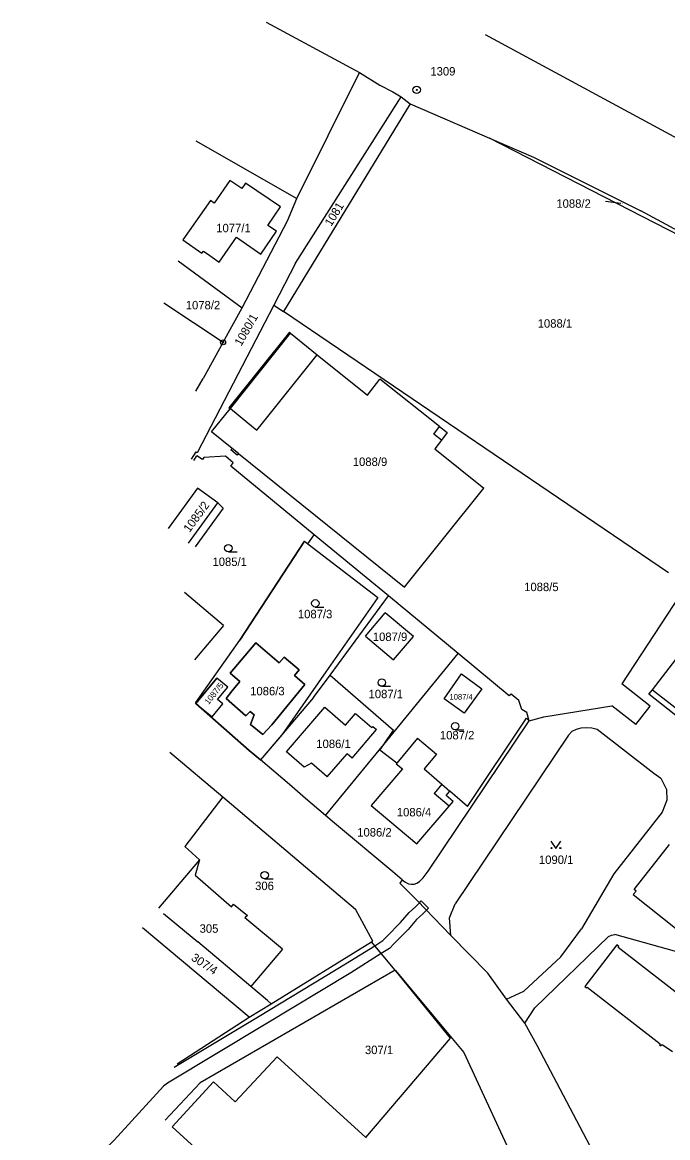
# Model space of a CAD drawing. Extents: x -621172 to -616925, y -1123899 to -1119548.
# Drawn here: x -619284.5 to -619154.3, y -1121538.1 to -1121313.2 of the extents above; entities that cross this region are included whole.
import ezdxf

# ---------------------------------------------------------------- set-up
doc = ezdxf.new("R2010")
doc.units = 0
for name, color, linetype in [('Vrstva 1', 7, 'Continuous'), ('Vrstva 16', 7, 'Continuous'), ('Vrstva 17', 7, 'Continuous'), ('Vrstva 18', 7, 'Continuous'), ('Vrstva 19', 7, 'Continuous'), ('Vrstva 24', 7, 'Continuous'), ('Vrstva 25', 7, 'Continuous'), ('Vrstva 4', 7, 'Continuous')]:
    doc.layers.add(name, color=color, linetype=linetype)

msp = doc.modelspace()

# ---------------------------------------------------------------- linework, layer by layer
at = {"layer": 'Vrstva 1'}
for points in [[(-619235.35, -1121313.15), (-619216.51, -1121323.27)], [(-619191.16, -1121315.58), (-619124.1, -1121351.82)], [(-619229.15, -1121348.66), (-619216.51, -1121323.27)], [(-619216.51, -1121323.27), (-619212.42, -1121325.82)], [(-619212.42, -1121325.82), (-619209.77, -1121327.14)], [(-619209.77, -1121327.14), (-619208.11, -1121328.19)], [(-619206.26, -1121329.56), (-619231.87, -1121371.5)], [(-619229.42, -1121361.74), (-619208.11, -1121328.19)], [(-619208.11, -1121328.19), (-619206.26, -1121329.56)], [(-619206.26, -1121329.56), (-619190.24, -1121336.5)], [(-619190.24, -1121336.5), (-619181.41, -1121340.33)], [(-619141.38, -1121361.62), (-619190.24, -1121336.5)], [(-619249.54, -1121337.02), (-619229.15, -1121348.66)], [(-619181.41, -1121340.33), (-619159.77, -1121351.16)], [(-619231.01, -1121353.19), (-619229.15, -1121348.66)], [(-619141.15, -1121361.2), (-619159.77, -1121351.16)], [(-619240.18, -1121370.71), (-619231.01, -1121353.19)], [(-619253.11, -1121361.27), (-619240.18, -1121370.71)], [(-619229.42, -1121361.74), (-619233.8, -1121370.19)], [(-619255.98, -1121369.71), (-619244.03, -1121377.68)], [(-619233.8, -1121370.19), (-619249.24, -1121399.95)], [(-619233.8, -1121370.19), (-619231.87, -1121371.5)], [(-619244.03, -1121377.68), (-619240.18, -1121370.71)], [(-619154.13, -1121424.18), (-619231.87, -1121371.5)], [(-619230.65, -1121375.66), (-619242.88, -1121390.93)], [(-619230.65, -1121375.66), (-619230.42, -1121375.85)], [(-619230.42, -1121375.85), (-619225.03, -1121380.24)], [(-619244.03, -1121377.68), (-619248.04, -1121384.95)], [(-619225.03, -1121380.24), (-619214.92, -1121388.32)], [(-619249.5, -1121387.56), (-619248.04, -1121384.95)], [(-619214.92, -1121388.32), (-619212.38, -1121385.12)], [(-619200.34, -1121394.66), (-619212.38, -1121385.12)], [(-619242.63, -1121391.11), (-619242.88, -1121390.93)], [(-619246.38, -1121395.76), (-619242.63, -1121391.11)], [(-619200.34, -1121394.66), (-619198.79, -1121395.89)], [(-619242.2, -1121399.12), (-619246.38, -1121395.76)], [(-619199.95, -1121397.4), (-619201.29, -1121399.14)], [(-619198.79, -1121395.89), (-619199.95, -1121397.4)], [(-619250.38, -1121401.22), (-619249.49, -1121399.8)], [(-619249.49, -1121399.8), (-619249.24, -1121399.95)], [(-619242.43, -1121399.4), (-619242.2, -1121399.12)], [(-619241.18, -1121400.44), (-619242.43, -1121399.4)], [(-619201.29, -1121399.14), (-619191.4, -1121407.08)], [(-619249.96, -1121401.49), (-619249.3, -1121400.59)], [(-619248.16, -1121401.32), (-619249.3, -1121400.59)], [(-619247.89, -1121400.92), (-619248.16, -1121401.32)], [(-619243.56, -1121400.66), (-619247.89, -1121400.92)], [(-619241.96, -1121402.01), (-619243.56, -1121400.66)], [(-619242.46, -1121402.65), (-619241.96, -1121402.01)], [(-619240.94, -1121400.13), (-619241.18, -1121400.44)], [(-619240.94, -1121400.13), (-619207.43, -1121427.07)], [(-619225.65, -1121416.5), (-619242.46, -1121402.65)], [(-619249.16, -1121407.09), (-619255.11, -1121415.21)], [(-619245.06, -1121410.04), (-619249.16, -1121407.09)], [(-619207.43, -1121427.07), (-619191.4, -1121407.08)], [(-619243.99, -1121411.15), (-619249.64, -1121418.96)], [(-619245.06, -1121410.04), (-619243.99, -1121411.15)], [(-619236.5, -1121461.91), (-619238.76, -1121459.99), (-619242.74, -1121456.53), (-619249.53, -1121450.52), (-619249.61, -1121450.46), (-619249.54, -1121450.33), (-619240.62, -1121437.73), (-619227.58, -1121417.81), (-619226.94, -1121418.3), (-619212.82, -1121429.18), (-619213.38, -1121430), (-619223.27, -1121444.13), (-619232.11, -1121456.77), (-619236.5, -1121461.91)], [(-619227.58, -1121417.81), (-619240.62, -1121437.73)], [(-619227.58, -1121417.81), (-619226.94, -1121418.3)], [(-619226.94, -1121418.3), (-619225.65, -1121416.5)], [(-619210.68, -1121428.84), (-619225.65, -1121416.5)], [(-619150.5, -1121426.64), (-619163.54, -1121446.57)], [(-619243.95, -1121434.77), (-619251.83, -1121428.12)], [(-619222.45, -1121444.84), (-619210.68, -1121428.84)], [(-619196.61, -1121440.44), (-619210.68, -1121428.84)], [(-619215.28, -1121436.97), (-619211.3, -1121432.23)], [(-619205.58, -1121437.03), (-619211.3, -1121432.23)], [(-619243.95, -1121434.77), (-619249.77, -1121441.7)], [(-619249.54, -1121450.33), (-619240.62, -1121437.73)], [(-619215.28, -1121436.97), (-619209.65, -1121441.72)], [(-619209.65, -1121441.72), (-619205.58, -1121437.03)], [(-619242.25, -1121448.02), (-619243.43, -1121449.5), (-619239.41, -1121453.03), (-619238.59, -1121452.15), (-619237.77, -1121452.84), (-619238.5, -1121454.75), (-619236, -1121456.77), (-619234.2, -1121454.83), (-619227.5, -1121446.69), (-619229.63, -1121444.88), (-619228.68, -1121443.75), (-619231.73, -1121441.15), (-619232.7, -1121442.3), (-619237.45, -1121438.29), (-619242.62, -1121444.42)], [(-619242.62, -1121444.42), (-619237.45, -1121438.29)], [(-619237.45, -1121438.29), (-619232.7, -1121442.3)], [(-619232.7, -1121442.3), (-619231.73, -1121441.15)], [(-619231.73, -1121441.15), (-619228.68, -1121443.75)], [(-619211.6, -1121458.78), (-619196.61, -1121440.44)], [(-619186.27, -1121448.96), (-619196.61, -1121440.44)], [(-619157.41, -1121447.76), (-619152.66, -1121441.64)], [(-619240.63, -1121446.1), (-619242.62, -1121444.42)], [(-619242.62, -1121444.42), (-619240.63, -1121446.1), (-619242.25, -1121448.02)], [(-619228.68, -1121443.75), (-619229.63, -1121444.88)], [(-619229.63, -1121444.88), (-619227.5, -1121446.69)], [(-619225.75, -1121449.33), (-619222.45, -1121444.84)], [(-619222.45, -1121444.84), (-619209.61, -1121455.88)], [(-619199.42, -1121449.57), (-619195.9, -1121444.57)], [(-619195.9, -1121444.57), (-619191.85, -1121447.56)], [(-619249.53, -1121450.52), (-619245.28, -1121445.39)], [(-619249.53, -1121450.52), (-619246.26, -1121453.23), (-619244.08, -1121450.57), (-619245.14, -1121449.71), (-619243.08, -1121447.21), (-619245.28, -1121445.39), (-619249.53, -1121450.52)], [(-619243.08, -1121447.21), (-619245.28, -1121445.39)], [(-619242.25, -1121448.02), (-619240.63, -1121446.1)], [(-619227.5, -1121446.69), (-619234.2, -1121454.83)], [(-619157.88, -1121451.07), (-619163.54, -1121446.57)], [(-619245.14, -1121449.71), (-619243.08, -1121447.21)], [(-619243.43, -1121449.5), (-619242.25, -1121448.02)], [(-619225.75, -1121449.33), (-619236.5, -1121461.91)], [(-619191.85, -1121447.56), (-619195.38, -1121452.46)], [(-619185.9, -1121448.62), (-619186.27, -1121448.96)], [(-619184.33, -1121449.91), (-619185.9, -1121448.62)], [(-619158.11, -1121448.67), (-619157.41, -1121447.76)], [(-619148.81, -1121455.94), (-619158.11, -1121448.67)], [(-619249.53, -1121450.52), (-619246.26, -1121453.23)], [(-619249.53, -1121450.52), (-619242.74, -1121456.53)], [(-619246.26, -1121453.23), (-619244.08, -1121450.57)], [(-619244.08, -1121450.57), (-619245.14, -1121449.71)], [(-619239.41, -1121453.03), (-619243.43, -1121449.5)], [(-619195.38, -1121452.46), (-619199.42, -1121449.57)], [(-619183.74, -1121451.74), (-619184.33, -1121449.91)], [(-619179.32, -1121453.23), (-619165.59, -1121450.99)], [(-619160.72, -1121454.77), (-619165.59, -1121450.99)], [(-619160.72, -1121454.77), (-619157.88, -1121451.07)], [(-619238.59, -1121452.15), (-619239.41, -1121453.03)], [(-619237.77, -1121452.84), (-619238.59, -1121452.15)], [(-619238.5, -1121454.75), (-619237.77, -1121452.84)], [(-619194.72, -1121471.3), (-619182.82, -1121453.5)], [(-619182.73, -1121452.33), (-619183.74, -1121451.74)], [(-619182.27, -1121454.01), (-619182.82, -1121453.5)], [(-619182.27, -1121454.01), (-619182.73, -1121452.33)], [(-619182.27, -1121454.01), (-619179.32, -1121453.23)], [(-619236, -1121456.77), (-619238.5, -1121454.75)], [(-619234.2, -1121454.83), (-619236, -1121456.77)], [(-619211.6, -1121458.78), (-619209.61, -1121455.88)], [(-619202.67, -1121484.33), (-619182.27, -1121454.01)], [(-619174.35, -1121456.88), (-619173.62, -1121456.1)], [(-619173.62, -1121456.1), (-619172.7, -1121455.7)], [(-619172.7, -1121455.7), (-619171.77, -1121455.45)], [(-619171.77, -1121455.45), (-619170.68, -1121455.35)], [(-619170.68, -1121455.35), (-619169.59, -1121455.41)], [(-619169.59, -1121455.41), (-619168.58, -1121455.72)], [(-619168.58, -1121455.72), (-619157.09, -1121464.57)], [(-619242.74, -1121456.53), (-619238.76, -1121459.99)], [(-619204.78, -1121457.51), (-619208.96, -1121462.53)], [(-619204.78, -1121457.51), (-619200.97, -1121460.75)], [(-619174.35, -1121456.88), (-619197.17, -1121490.9)], [(-619254.8, -1121460.36), (-619244.07, -1121469.36)], [(-619238.76, -1121459.99), (-619236.5, -1121461.91)], [(-619223.34, -1121473.08), (-619211.6, -1121458.78)], [(-619212.38, -1121459.91), (-619211.6, -1121458.78)], [(-619208.96, -1121462.53), (-619212.38, -1121459.91)], [(-619230.63, -1121466.86), (-619236.5, -1121461.91)], [(-619208.96, -1121462.53), (-619209.09, -1121462.68)], [(-619209.09, -1121462.68), (-619207.83, -1121463.71)], [(-619200.97, -1121460.75), (-619203.45, -1121463.68)], [(-619207.83, -1121463.71), (-619214.16, -1121471.09)], [(-619203.45, -1121463.68), (-619199.87, -1121466.82)], [(-619157.09, -1121464.57), (-619155.67, -1121465.6)], [(-619227.39, -1121469.68), (-619230.63, -1121466.86)], [(-619199.87, -1121466.82), (-619198.28, -1121468.19)], [(-619155.67, -1121465.6), (-619154.56, -1121467.9)], [(-619244.07, -1121469.36), (-619251.72, -1121479.37)], [(-619244.07, -1121469.36), (-619217.33, -1121491.98)], [(-619199.03, -1121469.06), (-619198.28, -1121468.19)], [(-619197.59, -1121470.29), (-619199.03, -1121469.06)], [(-619194.72, -1121471.3), (-619198.28, -1121468.19)], [(-619154.56, -1121467.9), (-619154.5, -1121470.02)], [(-619223.34, -1121473.08), (-619227.39, -1121469.68)], [(-619214.16, -1121471.09), (-619204.94, -1121478.85)], [(-619204.94, -1121478.85), (-619198.4, -1121471.25)], [(-619198.4, -1121471.25), (-619197.59, -1121470.29)], [(-619154.5, -1121470.02), (-619155.45, -1121472.46)], [(-619221.53, -1121474.68), (-619223.34, -1121473.08)], [(-619155.45, -1121472.46), (-619165.17, -1121484.88)], [(-619209.76, -1121484.49), (-619221.53, -1121474.68)], [(-619251.72, -1121479.37), (-619248.76, -1121482.04)], [(-619161.05, -1121488.05), (-619153.98, -1121478.94)], [(-619248.76, -1121482.04), (-619249.67, -1121485.15)], [(-619249.67, -1121485.15), (-619242.33, -1121491.54)], [(-619207.91, -1121486.06), (-619209.76, -1121484.49)], [(-619203.66, -1121485.66), (-619202.67, -1121484.33)], [(-619165.17, -1121484.88), (-619171.68, -1121495.98)], [(-619207.91, -1121486.06), (-619208.38, -1121486.77)], [(-619208.38, -1121486.77), (-619204.87, -1121490.25)], [(-619207.91, -1121486.06), (-619207.35, -1121486.51)], [(-619207.35, -1121486.51), (-619206.6, -1121486.9)], [(-619206.6, -1121486.9), (-619206.11, -1121486.96)], [(-619206.11, -1121486.96), (-619205.45, -1121486.93)], [(-619205.45, -1121486.93), (-619204.91, -1121486.74)], [(-619204.91, -1121486.74), (-619204.39, -1121486.43)], [(-619204.39, -1121486.43), (-619203.66, -1121485.66)], [(-619161.26, -1121489.06), (-619160.7, -1121488.34)], [(-619161.26, -1121489.06), (-619152.38, -1121496.1)], [(-619160.7, -1121488.34), (-619161.05, -1121488.05)], [(-619242.33, -1121491.54), (-619241.9, -1121491.01)], [(-619241.9, -1121491.01), (-619239.09, -1121493.29)], [(-619219.33, -1121503.05), (-619213.43, -1121499.36), (-619211.79, -1121498.33), (-619211.01, -1121497.5), (-619208.2, -1121494.72), (-619206.45, -1121492.68), (-619205.21, -1121491.52)], [(-619213.8, -1121498.44), (-619217.33, -1121491.98)], [(-619205.21, -1121491.52), (-619204.42, -1121490.72), (-619204.03, -1121490.33), (-619202.57, -1121491.79), (-619202.98, -1121492.21), (-619203.77, -1121493), (-619204.97, -1121494.1), (-619206.68, -1121496.12)], [(-619204.87, -1121490.25), (-619198.08, -1121497.29)], [(-619198.34, -1121493.75), (-619197.17, -1121490.9)], [(-619256.05, -1121492.85), (-619249.1, -1121498.56)], [(-619239.09, -1121493.29), (-619239.63, -1121493.76)], [(-619232.03, -1121500.09), (-619239.63, -1121493.76)], [(-619198.08, -1121497.29), (-619198.34, -1121493.75)], [(-619206.68, -1121496.12), (-619209.55, -1121498.96), (-619210.47, -1121499.93), (-619212.1, -1121500.95), (-619218.25, -1121504.81), (-619235.67, -1121515.33), (-619255.24, -1121527.06), (-619256.04, -1121527.68), (-619266.03, -1121538.58), (-619284, -1121557.05), (-619284.54, -1121557.73)], [(-619238.74, -1121513.79), (-619260.29, -1121495.79)], [(-619175.87, -1121501.61), (-619171.68, -1121495.98)], [(-619238.43, -1121507.57), (-619249.1, -1121498.56)], [(-619234.32, -1121511.07), (-619214.06, -1121498.6)], [(-619214.06, -1121498.6), (-619213.8, -1121498.44)], [(-619209.32, -1121504.28), (-619214.06, -1121498.6)], [(-619190.59, -1121504.93), (-619198.08, -1121497.29)], [(-619181.13, -1121511.88), (-619166.29, -1121497.48)], [(-619166.29, -1121497.48), (-619165.67, -1121497.22)], [(-619165.67, -1121497.22), (-619164.96, -1121497.14)], [(-619150.05, -1121501.29), (-619164.96, -1121497.14)], [(-619232.03, -1121500.09), (-619238.43, -1121507.57)], [(-619164.57, -1121499.22), (-619171.02, -1121507.58)], [(-619164.18, -1121499.54), (-619164.57, -1121499.22)], [(-619164.31, -1121499.7), (-619164.18, -1121499.54)], [(-619149.56, -1121511.19), (-619164.31, -1121499.7)], [(-619253.9, -1121523.86), (-619236.73, -1121513.57), (-619219.33, -1121503.05)], [(-619183.33, -1121508.53), (-619175.87, -1121501.61)], [(-619209.32, -1121504.28), (-619248.62, -1121527.02)], [(-619209.32, -1121504.28), (-619209.24, -1121504.37)], [(-619198.12, -1121518.02), (-619209.24, -1121504.37)], [(-619209.24, -1121504.37), (-619195.44, -1121520.9)], [(-619186.82, -1121510.16), (-619190.59, -1121504.93)], [(-619235.04, -1121510.4), (-619238.43, -1121507.57)], [(-619171.02, -1121507.58), (-619170.68, -1121507.85)], [(-619170.68, -1121507.85), (-619170.56, -1121507.7)], [(-619170.56, -1121507.7), (-619155.84, -1121519.17)], [(-619186.82, -1121510.16), (-619183.33, -1121508.53)], [(-619183.12, -1121514.99), (-619186.82, -1121510.16)], [(-619238.74, -1121513.79), (-619234.32, -1121511.07)], [(-619234.32, -1121511.07), (-619235.04, -1121510.4)], [(-619183.12, -1121514.99), (-619181.13, -1121511.88)], [(-619253.27, -1121523.19), (-619238.74, -1121513.79)], [(-619180.68, -1121519.47), (-619183.12, -1121514.99)], [(-619215.21, -1121538.04), (-619198.12, -1121518.02)], [(-619195.44, -1121520.9), (-619186, -1121541.43)], [(-619160.65, -1121557.4), (-619180.68, -1121519.47)], [(-619155.84, -1121519.17), (-619155.96, -1121519.33)], [(-619155.96, -1121519.33), (-619155.68, -1121519.55)], [(-619155.68, -1121519.55), (-619155.46, -1121519.27)], [(-619155.46, -1121519.27), (-619153.38, -1121520.7)], [(-619233.09, -1121521.8), (-619241.58, -1121530.84)], [(-619215.21, -1121538.04), (-619233.09, -1121521.8)], [(-619248.62, -1121527.02), (-619255.72, -1121534.56)], [(-619245.99, -1121526.84), (-619254.29, -1121535.87)], [(-619241.58, -1121530.84), (-619245.99, -1121526.84)], [(-619254.29, -1121535.87), (-619231.99, -1121556.27)], [(-619215.11, -1121538.13), (-619215.21, -1121538.04)]]:
    msp.add_lwpolyline(points, dxfattribs=at)
at = {"layer": 'Vrstva 16'}
msp.add_line((-619163.77, -1121349.69), (-619166.878, -1121349.261), dxfattribs=at)
at = {"layer": 'Vrstva 24'}
for centre, radius in [((-619204.96, -1121326.77), 0.75), ((-619204.96, -1121326.77), 0.1), ((-619244.03, -1121377.68), 0.5), ((-619244.03, -1121377.68), 0.1)]:
    msp.add_circle(centre, radius, dxfattribs=at)
at = {"layer": 'Vrstva 25'}
for p, q in [((-619242.96, -1121419.94), (-619241.21, -1121419.94)), ((-619225.42, -1121431.08), (-619223.67, -1121431.08)), ((-619212, -1121447.06), (-619210.25, -1121447.06)), ((-619197.21, -1121455.84), (-619195.46, -1121455.84)), ((-619235.64, -1121485.9), (-619233.89, -1121485.9))]:
    msp.add_line(p, q, dxfattribs=at)
msp.add_lwpolyline([(-619177.88, -1121478.28), (-619176.88, -1121479.78), (-619175.88, -1121478.28)], dxfattribs=at)
for centre, radius in [((-619242.96, -1121419.19), 0.75), ((-619225.42, -1121430.33), 0.75), ((-619212, -1121446.31), 0.75), ((-619197.21, -1121455.09), 0.75), ((-619177.78, -1121479.68), 0.1), ((-619175.982, -1121479.68), 0.1), ((-619235.64, -1121485.15), 0.75)]:
    msp.add_circle(centre, radius, dxfattribs=at)
at = {"layer": 'Vrstva 4'}
for points in [[(-619242.65, -1121345.05), (-619245.84, -1121349.62)], [(-619240.21, -1121346.67), (-619242.65, -1121345.05)], [(-619239.49, -1121345.58), (-619240.21, -1121346.67)], [(-619232.44, -1121350.35), (-619239.49, -1121345.58)], [(-619246.59, -1121349.1), (-619252.13, -1121357.05)], [(-619245.84, -1121349.62), (-619246.59, -1121349.1)], [(-619234.99, -1121354.12), (-619232.44, -1121350.35)], [(-619233.25, -1121355.3), (-619234.99, -1121354.12)], [(-619252.13, -1121357.05), (-619248.3, -1121359.72)], [(-619244.84, -1121361.49), (-619241.35, -1121356.48)], [(-619241.35, -1121356.48), (-619236.41, -1121359.93)], [(-619236.41, -1121359.93), (-619233.25, -1121355.3)], [(-619248.3, -1121359.72), (-619248.01, -1121359.29)], [(-619248.01, -1121359.29), (-619246.7, -1121360.19)], [(-619246.7, -1121360.19), (-619244.84, -1121361.49)], [(-619242.54, -1121391), (-619230.42, -1121375.85)], [(-619236.32, -1121394.33), (-619225.03, -1121380.24)], [(-619242.63, -1121391.11), (-619242.54, -1121391)], [(-619242.54, -1121391), (-619237.88, -1121394.85)], [(-619237.88, -1121394.85), (-619237.2, -1121395.42)], [(-619237.2, -1121395.42), (-619236.32, -1121394.33)], [(-619201.53, -1121396.24), (-619200.34, -1121394.66)], [(-619199.95, -1121397.4), (-619201.53, -1121396.24)], [(-619240.94, -1121400.13), (-619242.2, -1121399.12)], [(-619251, -1121418.18), (-619245.06, -1121410.04)], [(-619157.41, -1121447.76), (-619148.96, -1121454.32)], [(-619231.25, -1121460.28), (-619223.5, -1121451.27)], [(-619223.5, -1121451.27), (-619219.33, -1121454.86)], [(-619219.33, -1121454.86), (-619217.3, -1121452.51)], [(-619217.3, -1121452.51), (-619214.01, -1121455.34)], [(-619217.97, -1121461.53), (-619213.04, -1121455.8)], [(-619214.01, -1121455.34), (-619213.82, -1121455.13)], [(-619213.82, -1121455.13), (-619213.04, -1121455.8)], [(-619227.68, -1121463.35), (-619231.25, -1121460.28)], [(-619223, -1121465.28), (-619219, -1121460.65)], [(-619217.97, -1121461.53), (-619219, -1121460.65)], [(-619226.18, -1121462.53), (-619227.68, -1121463.35)], [(-619223, -1121465.28), (-619226.18, -1121462.53)], [(-619199.87, -1121466.82), (-619201.43, -1121468.64)], [(-619198.4, -1121471.25), (-619201.43, -1121468.64)], [(-619248.76, -1121482.04), (-619257.03, -1121491.81)]]:
    msp.add_lwpolyline(points, dxfattribs=at)

# ---------------------------------------------------------------- texts
at = {"layer": 'Vrstva 16'}
msp.add_text('1088/2', height=1.7, dxfattribs=at).set_placement((-619176.782, -1121350.55))
at = {"layer": 'Vrstva 17'}
msp.add_text('1309', height=1.7, dxfattribs=at).set_placement((-619202.203, -1121323.88))
at = {"layer": 'Vrstva 18'}
for s, rotation, p in [('1081', 58.5, (-619222.208, -1121354.429)), ('1080/1', 60.3, (-619240.365, -1121378.579)), ('307/4', 326.7, (-619250.613, -1121502.182))]:
    msp.add_text(s, height=1.7, rotation=rotation, dxfattribs=at).set_placement(p)
for s, height, p in [('1088/2', 0.1, (-619163.77, -1121349.69)), ('1078/2', 1.7, (-619251.557, -1121371.04)), ('1088/1', 1.7, (-619180.55, -1121374.73)), ('1085/1', 1.7, (-619246.172, -1121422.79)), ('1088/5', 1.7, (-619183.28, -1121427.86)), ('1087/3', 1.7, (-619228.939, -1121433.33)), ('1087/1', 1.7, (-619214.675, -1121449.45)), ('1087/2', 1.7, (-619200.277, -1121457.76)), ('1086/2', 1.7, (-619216.963, -1121477.35)), ('1090/1', 1.7, (-619180.3, -1121482.88)), ('306', 1.7, (-619237.565, -1121488.15)), ('307/1', 1.7, (-619215.407, -1121521.23))]:
    msp.add_text(s, height=height, dxfattribs=at).set_placement(p)
at = {"layer": 'Vrstva 19'}
for s, height, p in [('1077/1', 1.7, (-619245.406, -1121355.49)), ('1088/9', 1.7, (-619217.86, -1121402.62)), ('1087/9', 1.7, (-619213.822, -1121437.92)), ('1086/3', 1.7, (-619238.564, -1121448.87)), ('1087/4', 1.14, (-619198.328, -1121449.75)), ('1086/1', 1.7, (-619225.22, -1121459.51)), ('1086/4', 1.7, (-619208.978, -1121473.29)), ('305', 1.7, (-619248.766, -1121496.76))]:
    msp.add_text(s, height=height, dxfattribs=at).set_placement(p)
for s, height, rotation, p in [('1085/2', 1.7, 53.74611, (-619250.8, -1121416.159)), ('1087/5', 1.22, 51.3513, (-619246.941, -1121450.843))]:
    msp.add_text(s, height=height, rotation=rotation, dxfattribs=at).set_placement(p)

doc.saveas('drawing.dxf')
